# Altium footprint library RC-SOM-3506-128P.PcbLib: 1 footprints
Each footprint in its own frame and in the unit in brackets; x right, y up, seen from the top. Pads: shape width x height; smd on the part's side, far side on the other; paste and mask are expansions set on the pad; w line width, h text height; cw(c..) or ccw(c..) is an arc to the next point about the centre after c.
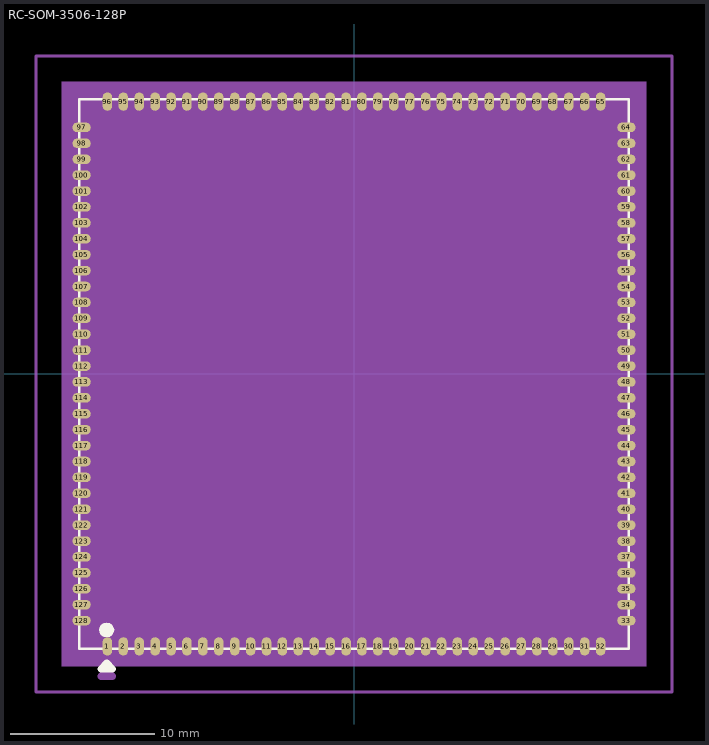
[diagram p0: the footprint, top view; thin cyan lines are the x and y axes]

## RC-SOM-3506-128P [mm] "SOM3506-128P"
pads (128):
  oval 0.66x1.27 smd: 1(-17.05,-18.835) 2(-15.95,-18.835) 3(-14.85,-18.835) 4(-13.75,-18.835) 5(-12.65,-18.835) 6(-11.55,-18.835) 7(-10.45,-18.835) 8(-9.35,-18.835) 9(-8.25,-18.835) 10(-7.15,-18.835) 11(-6.05,-18.835) 12(-4.95,-18.835) 13(-3.85,-18.835) 14(-2.75,-18.835) 15(-1.65,-18.835) 16(-0.55,-18.835) 17(0.55,-18.835) 18(1.65,-18.835) 19(2.75,-18.835) 20(3.85,-18.835) 21(4.95,-18.835) 22(6.05,-18.835) 23(7.15,-18.835) 24(8.25,-18.835) 25(9.35,-18.835) 26(10.45,-18.835) 27(11.55,-18.835) 28(12.65,-18.835) 29(13.75,-18.835) 30(14.85,-18.835) 31(15.95,-18.835) 32(17.05,-18.835) 65(17.05,18.835) 66(15.95,18.835) 67(14.85,18.835) 68(13.75,18.835) 69(12.65,18.835) 70(11.55,18.835) 71(10.45,18.835) 72(9.35,18.835) 73(8.25,18.835) 74(7.15,18.835) 75(6.05,18.835) 76(4.95,18.835) 77(3.85,18.835) 78(2.75,18.835) 79(1.65,18.835) 80(0.55,18.835) 81(-0.55,18.835) 82(-1.65,18.835) 83(-2.75,18.835) 84(-3.85,18.835) 85(-4.95,18.835) 86(-6.05,18.835) 87(-7.15,18.835) 88(-8.25,18.835) 89(-9.35,18.835) 90(-10.45,18.835) 91(-11.55,18.835) 92(-12.65,18.835) 93(-13.75,18.835) 94(-14.85,18.835) 95(-15.95,18.835) 96(-17.05,18.835)
  oval 1.27x0.66 smd: 33(18.835,-17.05) 34(18.835,-15.95) 35(18.835,-14.85) 36(18.835,-13.75) 37(18.835,-12.65) 38(18.835,-11.55) 39(18.835,-10.45) 40(18.835,-9.35) 41(18.835,-8.25) 42(18.835,-7.15) 43(18.835,-6.05) 44(18.835,-4.95) 45(18.835,-3.85) 46(18.835,-2.75) 47(18.835,-1.65) 48(18.835,-0.55) 49(18.835,0.55) 50(18.835,1.65) 51(18.835,2.75) 52(18.835,3.85) 53(18.835,4.95) 54(18.835,6.05) 55(18.835,7.15) 56(18.835,8.25) 57(18.835,9.35) 58(18.835,10.45) 59(18.835,11.55) 60(18.835,12.65) 61(18.835,13.75) 62(18.835,14.85) 63(18.835,15.95) 64(18.835,17.05) 97(-18.835,17.05) 98(-18.835,15.95) 99(-18.835,14.85) 100(-18.835,13.75) 101(-18.835,12.65) 102(-18.835,11.55) 103(-18.835,10.45) 104(-18.835,9.35) 105(-18.835,8.25) 106(-18.835,7.15) 107(-18.835,6.05) 108(-18.835,4.95) 109(-18.835,3.85) 110(-18.835,2.75) 111(-18.835,1.65) 112(-18.835,0.55) 113(-18.835,-0.55) 114(-18.835,-1.65) 115(-18.835,-2.75) 116(-18.835,-3.85) 117(-18.835,-4.95) 118(-18.835,-6.05) 119(-18.835,-7.15) 120(-18.835,-8.25) 121(-18.835,-9.35) 122(-18.835,-10.45) 123(-18.835,-11.55) 124(-18.835,-12.65) 125(-18.835,-13.75) 126(-18.835,-14.85) 127(-18.835,-15.95) 128(-18.835,-17.05)
Top Overlay:
  dashed: -17.1,-18.21 -16.905,-18.171 -16.74,-18.06 -16.629,-17.895 -16.59,-17.7 -16.629,-17.505 -16.666,-17.449 -16.74,-17.34 -16.905,-17.229 -17.1,-17.19 -17.295,-17.229 -17.46,-17.34 -17.534,-17.449 -17.571,-17.505 -17.61,-17.7 -17.571,-17.895 -17.46,-18.06 -17.295,-18.171
  lines w0.2: -19,-19 -19,19 19,19 19,-19 -19,-19
  lines w0.5: -17.5,-20.392 -16.7,-20.392 -17.1,-19.992 -17.5,-20.392
  text ".Designator" at -17.526,-21.717 h0.64
Top Assembly:
  dashed: -17.1,-18.21 -16.905,-18.171 -16.74,-18.06 -16.629,-17.895 -16.59,-17.7 -16.629,-17.505 -16.666,-17.449 -16.74,-17.34 -16.905,-17.229 -17.1,-17.19 -17.295,-17.229 -17.46,-17.34 -17.534,-17.449 -17.571,-17.505 -17.61,-17.7 -17.571,-17.895 -17.46,-18.06 -17.295,-18.171
  lines w0.2: -22,-22 -22,22 22,22 22,-22 -22,-22 ; -19,-19 -19,19 19,19 19,-19 -19,-19
  lines w0.5: -17.5,-20.9 -16.7,-20.9 -17.1,-20.5 -17.5,-20.9
Top 3D Body:
  region: -20.2,-20.2 -20.2,20.2 20.2,20.2 20.2,-20.2
Mechanical 15:
  text "35" at 18.835,-12.564 h0.64
  text "44" at 18.835,-2.664 h0.64
  text "48" at 18.835,1.736 h0.64
  text "61" at 18.835,16.036 h0.64
  text "23" at 8.42,-17.819 h0.64
  text "17" at 1.82,-17.819 h0.64
  text "15" at -0.38,-17.819 h0.64
  text "82" at -2.92,19.851 h0.64
  text "12" at -3.68,-17.819 h0.64
  text "10" at -5.88,-17.819 h0.64
  text "87" at -8.42,19.851 h0.64
  text "90" at -11.72,19.851 h0.64
  text "5" at -11.38,-18.327 h0.64
  text "124" at -18.835,-12.396 h0.64
  text "110" at -18.835,3.004 h0.64
  text "105" at -18.835,8.504 h0.64
  text "97" at -18.835,16.796 h0.64
  text "115" at -18.835,-2.496 h0.64
  text "100" at -18.835,14.004 h0.64
  text "75" at 4.78,19.851 h0.64
  text "67" at 13.58,19.851 h0.64
  text "32" at 18.32,-17.819 h0.64
  text "65" at 15.78,19.851 h0.64
  text "66" at 14.68,19.851 h0.64
  text "43" at 18.835,-3.764 h0.64
  text "60" at 18.835,14.936 h0.64
  text "59" at 18.835,13.836 h0.64
  text "49" at 18.835,2.836 h0.64
  text "37" at 18.835,-10.364 h0.64
  text "47" at 18.835,0.636 h0.64
  text "38" at 18.835,-9.264 h0.64
  text "103" at -18.835,10.704 h0.64
  text "104" at -18.835,9.604 h0.64
  text "101" at -18.835,12.904 h0.64
  text "98" at -18.835,15.696 h0.64
  text "52" at 18.835,6.136 h0.64
  text "99" at -18.835,14.596 h0.64
  text "51" at 18.835,5.036 h0.64
  text "54" at 18.835,8.336 h0.64
  text "57" at 18.835,11.636 h0.64
  text "53" at 18.835,7.236 h0.64
  text "56" at 18.835,10.536 h0.64
  text "55" at 18.835,9.436 h0.64
  text "58" at 18.835,12.736 h0.64
  text "92" at -13.92,19.851 h0.64
  text "91" at -12.82,19.851 h0.64
  text "95" at -17.22,19.851 h0.64
  text "96" at -18.32,19.851 h0.64
  text "102" at -18.835,11.804 h0.64
  text "73" at 6.98,19.851 h0.64
  text "72" at 8.08,19.851 h0.64
  text "74" at 5.88,19.851 h0.64
  text "71" at 9.18,19.851 h0.64
  text "70" at 10.28,19.851 h0.64
  text "69" at 11.38,19.851 h0.64
  text "62" at 18.835,17.136 h0.64
  text "64" at 18.835,19.336 h0.64
  text "86" at -7.32,19.851 h0.64
  text "85" at -6.22,19.851 h0.64
  text "13" at -2.58,-17.819 h0.64
  text "63" at 18.835,18.236 h0.64
  text "21" at 6.22,-17.819 h0.64
  text "36" at 18.835,-11.464 h0.64
  text "31" at 17.22,-17.819 h0.64
  text "30" at 16.12,-17.819 h0.64
  text "20" at 5.12,-17.819 h0.64
  text "29" at 15.02,-17.819 h0.64
  text "28" at 13.92,-17.819 h0.64
  text "27" at 12.82,-17.819 h0.64
  text "41" at 18.835,-5.964 h0.64
  text "14" at -1.48,-17.819 h0.64
  text "45" at 18.835,-1.564 h0.64
  text "50" at 18.835,3.936 h0.64
  text "19" at 4.02,-17.819 h0.64
  text "18" at 2.92,-17.819 h0.64
  text "40" at 18.835,-7.064 h0.64
  text "22" at 7.32,-17.819 h0.64
  text "24" at 9.52,-17.819 h0.64
  text "39" at 18.835,-8.164 h0.64
  text "93" at -15.02,19.851 h0.64
  text "16" at 0.72,-17.819 h0.64
  text "94" at -16.12,19.851 h0.64
  text "42" at 18.835,-4.864 h0.64
  text "25" at 10.62,-17.819 h0.64
  text "11" at -4.78,-17.819 h0.64
  text "46" at 18.835,-0.464 h0.64
  text "126" at -18.835,-14.596 h0.64
  text "127" at -18.835,-15.696 h0.64
  text "34" at 18.835,-13.664 h0.64
  text "33" at 18.835,-14.764 h0.64
  text "106" at -18.835,7.404 h0.64
  text "107" at -18.835,6.304 h0.64
  text "108" at -18.835,5.204 h0.64
  text "109" at -18.835,4.104 h0.64
  text "111" at -18.835,1.904 h0.64
  text "112" at -18.835,0.804 h0.64
  text "113" at -18.835,-0.296 h0.64
  text "114" at -18.835,-1.396 h0.64
  text "116" at -18.835,-3.596 h0.64
  text "120" at -18.835,-7.996 h0.64
  text "121" at -18.835,-9.096 h0.64
  text "122" at -18.835,-10.196 h0.64
  text "123" at -18.835,-11.296 h0.64
  text "125" at -18.835,-13.496 h0.64
  text "1" at -15.78,-18.327 h0.64
  text "2" at -14.68,-18.327 h0.64
  text "3" at -13.58,-18.327 h0.64
  text "4" at -12.48,-18.327 h0.64
  text "6" at -10.28,-18.327 h0.64
  text "118" at -18.835,-5.796 h0.64
  text "119" at -18.835,-6.896 h0.64
  text "68" at 12.48,19.851 h0.64
  text "83" at -4.02,19.851 h0.64
  text "84" at -5.12,19.851 h0.64
  text "26" at 11.72,-17.819 h0.64
  text "88" at -9.52,19.851 h0.64
  text "89" at -10.62,19.851 h0.64
  text "9" at -6.98,-18.327 h0.64
  text "8" at -8.08,-18.327 h0.64
  text "7" at -9.18,-18.327 h0.64
  text "81" at -1.82,19.851 h0.64
  text "76" at 3.68,19.851 h0.64
  text "77" at 2.58,19.851 h0.64
  text "80" at -0.72,19.851 h0.64
  text "79" at 0.38,19.851 h0.64
  text "78" at 1.48,19.851 h0.64
  text "128" at -18.835,-16.796 h0.64
  text "117" at -18.835,-4.696 h0.64
3D body: height 3.81, standoff 0, extent -20.2,-20.2 20.2,20.2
